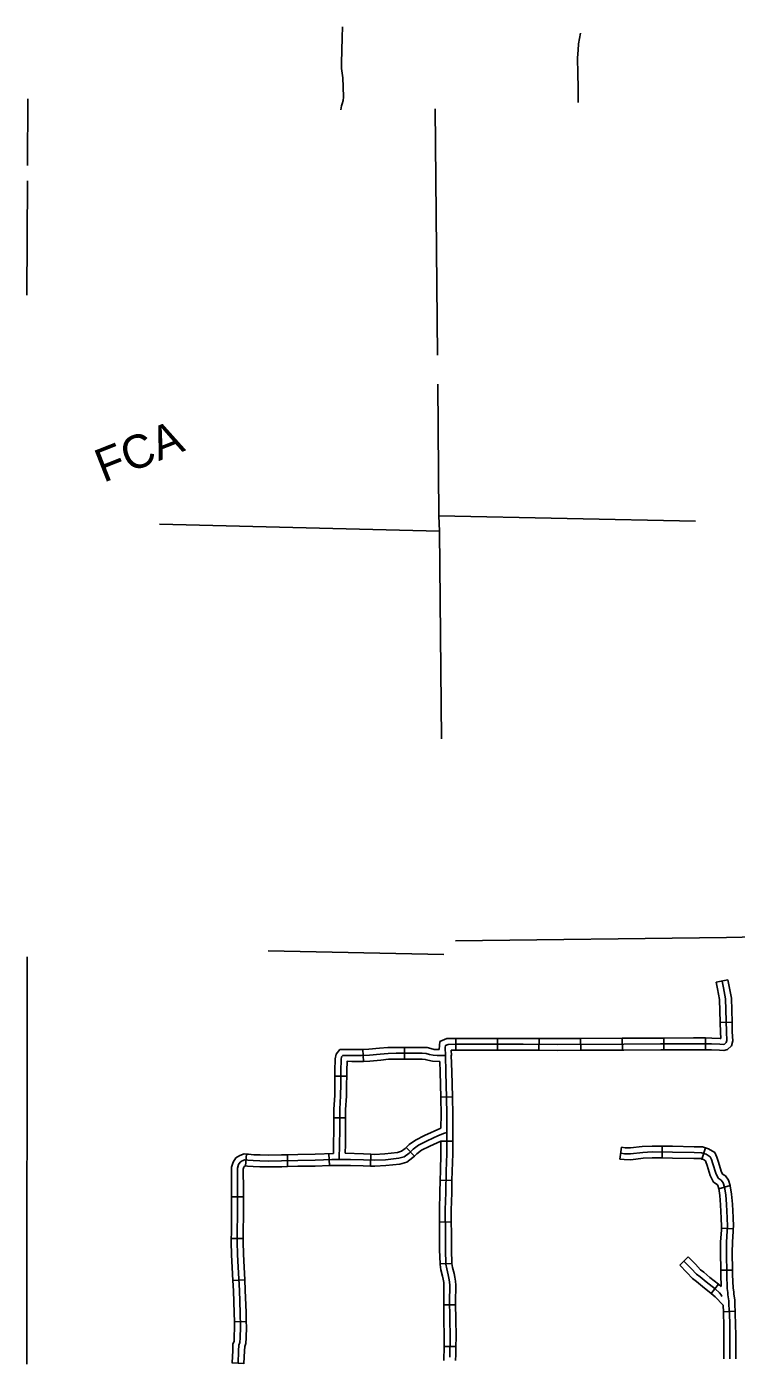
# Model space of a CAD drawing. Extents: x 1127717 to 1741049, y 2026793 to 2244711.
# Drawn here: x 1491449 to 1500445, y 2189590 to 2206550 of the extents above; entities that cross this region are included whole.
import ezdxf

# ---------------------------------------------------------------- set-up
doc = ezdxf.new("R2010")
doc.units = 0
for name, color, linetype in [('26', 7, 'Continuous'), ('32', 7, 'Continuous'), ('4', 7, 'Continuous'), ('5', 7, 'Continuous')]:
    doc.layers.add(name, color=color, linetype=linetype)

msp = doc.modelspace()

# ---------------------------------------------------------------- linework, layer by layer
at = {"layer": '32'}
for p, q in [((1500192, 2194434), (1500339, 2194463)), ((1500242, 2193923), (1500392, 2193926)), ((1495717, 2193430), (1495710, 2193580)), ((1496240, 2193458), (1496240, 2193608)), ((1496888, 2193722), (1496888, 2193572)), ((1497416, 2193722), (1497416, 2193572)), ((1497945, 2193721), (1497944, 2193571)), ((1498472, 2193721), (1498473, 2193571)), ((1499000, 2193724), (1499001, 2193574)), ((1499528, 2193726), (1499529, 2193576)), ((1500057, 2193727), (1500055, 2193577)), ((1495506, 2193242), (1495356, 2193243)), ((1496698, 2192976), (1496848, 2192980)), ((1495492, 2192715), (1495342, 2192715)), ((1496701, 2192420), (1496851, 2192420)), ((1494234, 2192255), (1494222, 2192105)), ((1494754, 2192247), (1494757, 2192097)), ((1495280, 2192259), (1495286, 2192109)), ((1495813, 2192253), (1495809, 2192103)), ((1496261, 2192338), (1496365, 2192230)), ((1498971, 2192192), (1498989, 2192341)), ((1499505, 2192206), (1499507, 2192356)), ((1500011, 2192192), (1500055, 2192335)), ((1496691, 2191924), (1496841, 2191920)), ((1494047, 2191713), (1494197, 2191713)), ((1500224, 2191815), (1500368, 2191858)), ((1496682, 2191393), (1496832, 2191395)), ((1500259, 2191315), (1500408, 2191306)), ((1494043, 2191186), (1494193, 2191184)), ((1496690, 2190864), (1496840, 2190869)), ((1499728, 2190846), (1499834, 2190952)), ((1500249, 2190782), (1500399, 2190784)), ((1494063, 2190653), (1494213, 2190661)), ((1500128, 2190489), (1500220, 2190607)), ((1496737, 2190342), (1496887, 2190344)), ((1500283, 2190253), (1500432, 2190261)), ((1494082, 2190128), (1494232, 2190131)), ((1496740, 2189816), (1496890, 2189814)), ((1494053, 2189608), (1494203, 2189601))]:
    msp.add_line(p, q, dxfattribs=at)
for points in [[(1495452, 2206550), (1495448, 2206415), (1495444, 2206249), (1495442, 2206093), (1495442, 2206019), (1495449, 2205960), (1495456, 2205901), (1495460, 2205788), (1495464, 2205655), (1495460, 2205613), (1495447, 2205572), (1495440, 2205546), (1495436, 2205522), (1495432, 2205495)], [(1498472, 2206467), (1498446, 2206334), (1498440, 2206254), (1498434, 2206154), (1498437, 2205951), (1498440, 2205780), (1498440, 2205619), (1498443, 2205588)], [(1500266, 2194448), (1500282, 2194364), (1500310, 2194222), (1500320, 2193804), (1500325, 2193696), (1500318, 2193668), (1500297, 2193649), (1500278, 2193643), (1500236, 2193647), (1500132, 2193651), (1499902, 2193653), (1499486, 2193651), (1499019, 2193649), (1498175, 2193645), (1497745, 2193647), (1497388, 2193647), (1496887, 2193647), (1496791, 2193645), (1496758, 2193630), (1496756, 2193607), (1496758, 2193506)], [(1500192, 2194434), (1500209, 2194350), (1500235, 2194214), (1500242, 2193923)], [(1500339, 2194463), (1500356, 2194379), (1500385, 2194231), (1500392, 2193926)], [(1500392, 2193926), (1500395, 2193806), (1500400, 2193689), (1500386, 2193628), (1500336, 2193583), (1500287, 2193567), (1500231, 2193572), (1500130, 2193576), (1500055, 2193577)], [(1500242, 2193923), (1500245, 2193801), (1500249, 2193721), (1500241, 2193722), (1500134, 2193726), (1500057, 2193727)], [(1495356, 2193243), (1495357, 2193312), (1495360, 2193463), (1495371, 2193522), (1495421, 2193582), (1495475, 2193582), (1495571, 2193579), (1495694, 2193579), (1495710, 2193580)], [(1495710, 2193580), (1495788, 2193584), (1495924, 2193596), (1496027, 2193607), (1496134, 2193608), (1496240, 2193608)], [(1496240, 2193608), (1496306, 2193608), (1496466, 2193608), (1496526, 2193605), (1496571, 2193592), (1496615, 2193583), (1496657, 2193581), (1496678, 2193581)], [(1496888, 2193722), (1496886, 2193722), (1496775, 2193720), (1496687, 2193681), (1496678, 2193581)], [(1497416, 2193722), (1497388, 2193722), (1496888, 2193722)], [(1497945, 2193721), (1497745, 2193722), (1497416, 2193722)], [(1498472, 2193721), (1498175, 2193720), (1497945, 2193721)], [(1499000, 2193724), (1498472, 2193721)], [(1499528, 2193726), (1499486, 2193726), (1499019, 2193724), (1499000, 2193724)], [(1500057, 2193727), (1499902, 2193728), (1499528, 2193726)], [(1500055, 2193577), (1499902, 2193578), (1499529, 2193576)], [(1495410, 2192187), (1495415, 2192379), (1495417, 2192556), (1495417, 2192824), (1495429, 2192993), (1495430, 2193143), (1495432, 2193311), (1495435, 2193455), (1495441, 2193489), (1495456, 2193507), (1495473, 2193507), (1495570, 2193504), (1495695, 2193504), (1495793, 2193509), (1495931, 2193521), (1496032, 2193532), (1496135, 2193533), (1496306, 2193533), (1496464, 2193533), (1496514, 2193530), (1496554, 2193519), (1496604, 2193509), (1496655, 2193506), (1496758, 2193506)], [(1495506, 2193242), (1495507, 2193310), (1495510, 2193431), (1495569, 2193429), (1495697, 2193429), (1495717, 2193430)], [(1495717, 2193430), (1495798, 2193434), (1495938, 2193446), (1496037, 2193457), (1496135, 2193458), (1496240, 2193458)], [(1496240, 2193458), (1496306, 2193458), (1496461, 2193458), (1496502, 2193456), (1496536, 2193446), (1496594, 2193434), (1496685, 2193429)], [(1496685, 2193429), (1496690, 2193292), (1496698, 2192976)], [(1496758, 2193506), (1496765, 2193294), (1496773, 2192967), (1496777, 2192763), (1496776, 2192528), (1496776, 2192257), (1496769, 2192040), (1496762, 2191766), (1496756, 2191546), (1496759, 2191254), (1496759, 2191041), (1496765, 2190860), (1496774, 2190801), (1496794, 2190723), (1496803, 2190682), (1496811, 2190634), (1496814, 2190590), (1496814, 2190553), (1496811, 2190414), (1496814, 2190169), (1496817, 2189934), (1496814, 2189716), (1496812, 2189680)], [(1496888, 2193572), (1496887, 2193572), (1496831, 2193571), (1496833, 2193507)], [(1496832, 2193508), (1496840, 2193297), (1496848, 2192980)], [(1497416, 2193572), (1497388, 2193572), (1496888, 2193572)], [(1497944, 2193571), (1497745, 2193572), (1497416, 2193572)], [(1498473, 2193571), (1498175, 2193570), (1497944, 2193571)], [(1499001, 2193574), (1498473, 2193571)], [(1499529, 2193576), (1499487, 2193576), (1499019, 2193574), (1499001, 2193574)], [(1495342, 2192715), (1495342, 2192826), (1495354, 2192996), (1495355, 2193143), (1495356, 2193243)], [(1495492, 2192715), (1495492, 2192821), (1495504, 2192990), (1495505, 2193142), (1495506, 2193242)], [(1496698, 2192976), (1496698, 2192965), (1496702, 2192762), (1496701, 2192585)], [(1496848, 2192980), (1496848, 2192968), (1496852, 2192764), (1496851, 2192528), (1496851, 2192450)], [(1495337, 2192261), (1495340, 2192381), (1495342, 2192556), (1495342, 2192715)], [(1495487, 2192265), (1495490, 2192378), (1495492, 2192555), (1495492, 2192715)], [(1496701, 2192585), (1496494, 2192490), (1496377, 2192432), (1496299, 2192375), (1496261, 2192338)], [(1496776, 2192528), (1496747, 2192522), (1496670, 2192489), (1496526, 2192423), (1496416, 2192368), (1496347, 2192317), (1496297, 2192268), (1496236, 2192222), (1496165, 2192201), (1495996, 2192184), (1495860, 2192176), (1495719, 2192181), (1495555, 2192187), (1495410, 2192187), (1495316, 2192185), (1495107, 2192178), (1494887, 2192175), (1494680, 2192170), (1494514, 2192167), (1494406, 2192169), (1494322, 2192172), (1494253, 2192178), (1494215, 2192181), (1494181, 2192169), (1494154, 2192152), (1494134, 2192121), (1494120, 2192077), (1494120, 2192010), (1494122, 2191851), (1494122, 2191688), (1494122, 2191505), (1494119, 2191251), (1494117, 2191143), (1494122, 2190982), (1494129, 2190820), (1494145, 2190525), (1494155, 2190242), (1494159, 2190064), (1494155, 2189926), (1494152, 2189867), (1494139, 2189830), (1494136, 2189762), (1494128, 2189601)], [(1496701, 2192420), (1496559, 2192355), (1496455, 2192303), (1496396, 2192260), (1496365, 2192230)], [(1496701, 2192420), (1496701, 2192258), (1496694, 2192042), (1496691, 2191924)], [(1496851, 2192450), (1496851, 2192256), (1496844, 2192038), (1496841, 2191920)], [(1494234, 2192255), (1494205, 2192257), (1494149, 2192237), (1494100, 2192207), (1494065, 2192153), (1494045, 2192088), (1494045, 2192010), (1494047, 2191850), (1494047, 2191713)], [(1494754, 2192247), (1494679, 2192245), (1494513, 2192242), (1494408, 2192244), (1494327, 2192247), (1494260, 2192253), (1494234, 2192255)], [(1495337, 2192261), (1495105, 2192253), (1494886, 2192250), (1494754, 2192247)], [(1495813, 2192253), (1495721, 2192256), (1495487, 2192265)], [(1496365, 2192230), (1496346, 2192211), (1496270, 2192154), (1496180, 2192127), (1496002, 2192109), (1495861, 2192101), (1495809, 2192103)], [(1496261, 2192338), (1496248, 2192325), (1496201, 2192290), (1496150, 2192275), (1495990, 2192259), (1495859, 2192251), (1495813, 2192253)], [(1498980, 2192267), (1499030, 2192260), (1499106, 2192257), (1499260, 2192276), (1499379, 2192282), (1499637, 2192279), (1499910, 2192273), (1500006, 2192272), (1500062, 2192255), (1500113, 2192222), (1500130, 2192186), (1500148, 2192132), (1500185, 2192013), (1500214, 2191951), (1500256, 2191924), (1500280, 2191891), (1500297, 2191835), (1500313, 2191737), (1500321, 2191616), (1500331, 2191446), (1500335, 2191337), (1500332, 2191283), (1500322, 2191140), (1500320, 2191009), (1500324, 2190727), (1500331, 2190549), (1500338, 2190500), (1500340, 2190470), (1500348, 2190420), (1500352, 2190394), (1500353, 2190338), (1500358, 2190239), (1500362, 2190089), (1500363, 2189963), (1500363, 2189658)], [(1498989, 2192341), (1499037, 2192335), (1499103, 2192332), (1499253, 2192351), (1499378, 2192357), (1499507, 2192356)], [(1499507, 2192356), (1499638, 2192354), (1499912, 2192348), (1500018, 2192346), (1500055, 2192335)], [(1500055, 2192335), (1500093, 2192323), (1500172, 2192273), (1500200, 2192214), (1500220, 2192154), (1500255, 2192040), (1500273, 2192002), (1500308, 2191979), (1500348, 2191925), (1500368, 2191858)], [(1494225, 2192105), (1494214, 2192101), (1494208, 2192097), (1494203, 2192089), (1494195, 2192065), (1494195, 2192010), (1494197, 2191851), (1494197, 2191713)], [(1494757, 2192097), (1494682, 2192095), (1494514, 2192092), (1494405, 2192094), (1494318, 2192097), (1494247, 2192103), (1494222, 2192105)], [(1495286, 2192109), (1495108, 2192103), (1494888, 2192100), (1494757, 2192097)], [(1495809, 2192103), (1495716, 2192106), (1495554, 2192112), (1495410, 2192112), (1495318, 2192110), (1495286, 2192109)], [(1498971, 2192192), (1499024, 2192185), (1499109, 2192182), (1499266, 2192201), (1499381, 2192207), (1499505, 2192206)], [(1499505, 2192206), (1499636, 2192204), (1499909, 2192198), (1499995, 2192197), (1500011, 2192192)], [(1500011, 2192192), (1500030, 2192186), (1500055, 2192170), (1500061, 2192158), (1500077, 2192109), (1500114, 2191985), (1500156, 2191900), (1500203, 2191869), (1500212, 2191857), (1500224, 2191815)], [(1496691, 2191924), (1496687, 2191768), (1496681, 2191547), (1496682, 2191393)], [(1496841, 2191920), (1496837, 2191764), (1496831, 2191545), (1496832, 2191395)], [(1494047, 2191713), (1494047, 2191688), (1494047, 2191505), (1494044, 2191252), (1494043, 2191186)], [(1494197, 2191713), (1494197, 2191688), (1494197, 2191504), (1494194, 2191250), (1494193, 2191184)], [(1500224, 2191818), (1500238, 2191728), (1500246, 2191611), (1500256, 2191443), (1500260, 2191338), (1500259, 2191315)], [(1500368, 2191858), (1500370, 2191852), (1500387, 2191746), (1500396, 2191621), (1500406, 2191450), (1500410, 2191336), (1500408, 2191306)], [(1496682, 2191393), (1496684, 2191253), (1496684, 2191040), (1496690, 2190864)], [(1496832, 2191395), (1496834, 2191254), (1496834, 2191042), (1496840, 2190869)], [(1500259, 2191315), (1500257, 2191288), (1500247, 2191143), (1500245, 2191009), (1500249, 2190782)], [(1500408, 2191306), (1500407, 2191278), (1500397, 2191137), (1500395, 2191009), (1500399, 2190784)], [(1494043, 2191186), (1494042, 2191142), (1494047, 2190979), (1494055, 2190816), (1494063, 2190653)], [(1494193, 2191184), (1494192, 2191143), (1494197, 2190985), (1494204, 2190823), (1494213, 2190661)], [(1496690, 2190864), (1496690, 2190853), (1496700, 2190786), (1496721, 2190706), (1496729, 2190668), (1496736, 2190626), (1496739, 2190587), (1496739, 2190554), (1496736, 2190414), (1496737, 2190342)], [(1496840, 2190869), (1496840, 2190867), (1496848, 2190816), (1496867, 2190741), (1496877, 2190696), (1496885, 2190643), (1496889, 2190593), (1496889, 2190552), (1496886, 2190414), (1496887, 2190344)], [(1499781, 2190899), (1499873, 2190806), (1499941, 2190733), (1499988, 2190698), (1500064, 2190634), (1500177, 2190545), (1500231, 2190497), (1500255, 2190472), (1500264, 2190449)], [(1499834, 2190952), (1499927, 2190858), (1499991, 2190789), (1500034, 2190757), (1500111, 2190692), (1500220, 2190607)], [(1499728, 2190846), (1499819, 2190754), (1499890, 2190677), (1499941, 2190640), (1500017, 2190575), (1500128, 2190489)], [(1500249, 2190782), (1500250, 2190725), (1500255, 2190577)], [(1500399, 2190784), (1500399, 2190729), (1500406, 2190556), (1500413, 2190508), (1500415, 2190479), (1500422, 2190431), (1500427, 2190401), (1500428, 2190341), (1500432, 2190261)], [(1494063, 2190653), (1494070, 2190522), (1494081, 2190240), (1494082, 2190128)], [(1494213, 2190661), (1494220, 2190528), (1494230, 2190244), (1494232, 2190131)], [(1500220, 2190607), (1500226, 2190603), (1500255, 2190577)], [(1500128, 2190489), (1500129, 2190488), (1500179, 2190443), (1500278, 2190339)], [(1496737, 2190342), (1496739, 2190168), (1496742, 2189934), (1496740, 2189816)], [(1496887, 2190344), (1496889, 2190170), (1496892, 2189934), (1496890, 2189814)], [(1500278, 2190339), (1500278, 2190335), (1500283, 2190253)], [(1500283, 2190253), (1500283, 2190236), (1500287, 2190087), (1500288, 2189963), (1500288, 2189658)], [(1500432, 2190261), (1500433, 2190242), (1500437, 2190090), (1500438, 2189964), (1500438, 2189659)], [(1494082, 2190128), (1494084, 2190064), (1494081, 2189929), (1494078, 2189882), (1494064, 2189845), (1494061, 2189766), (1494053, 2189608)], [(1494232, 2190131), (1494234, 2190064), (1494230, 2189923), (1494227, 2189851), (1494213, 2189815), (1494210, 2189759), (1494203, 2189601)], [(1496740, 2189816), (1496738, 2189637)], [(1496890, 2189814), (1496889, 2189714), (1496885, 2189638)], [(1494053, 2189608), (1494053, 2189604)], [(1494203, 2189601), (1494203, 2189597)]]:
    msp.add_lwpolyline(points, dxfattribs=at)
at = {"layer": '4'}
for points in [[(1496627, 2205507), (1496657, 2202387)], [(1496660, 2202017), (1496676, 2200347), (1496682, 2200155), (1496706, 2197519)]]:
    msp.add_lwpolyline(points, dxfattribs=at)
at = {"layer": '5'}
for points in [[(1491465, 2205634), (1491460, 2204792)], [(1491458, 2204595), (1491449, 2203147)], [(1496682, 2200155), (1493131, 2200241)], [(1499930, 2200282), (1496676, 2200347)], [(1502917, 2195058), (1500320, 2195000), (1496884, 2194959)], [(1496737, 2194787), (1494512, 2194830)], [(1491455, 2194757), (1491450, 2189590)]]:
    msp.add_lwpolyline(points, dxfattribs=at)

# ---------------------------------------------------------------- texts
at = {"layer": '26'}
msp.add_text('FCA', height=422.4, rotation=21.5153, dxfattribs=at).set_placement((1492422, 2200765))

doc.saveas('drawing.dxf')
